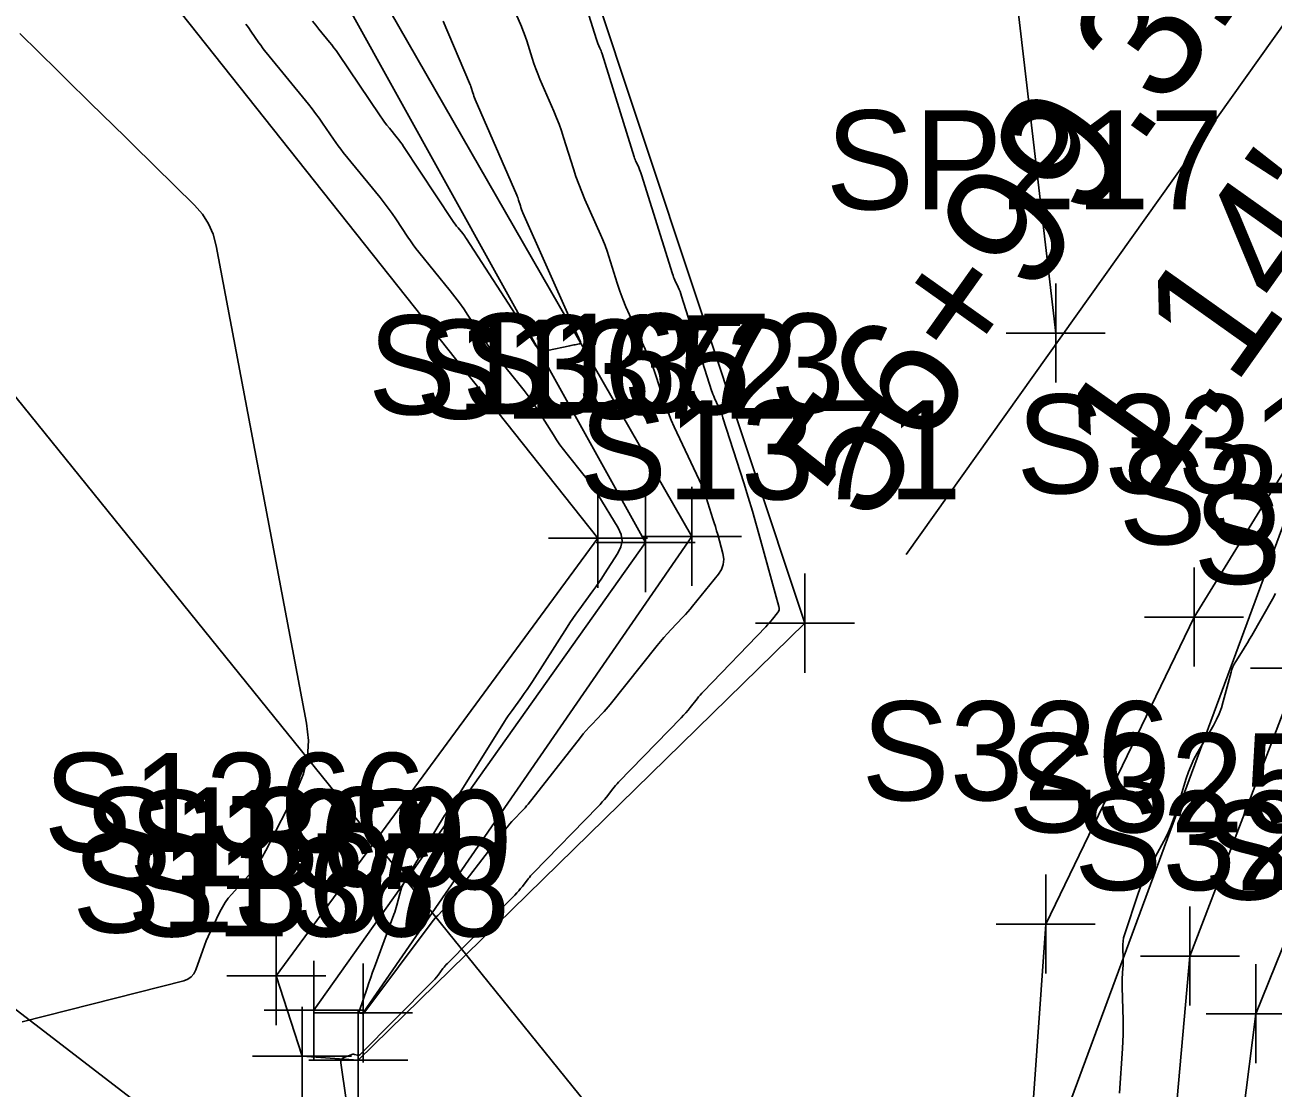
# Model space of a CAD drawing. Extents: x 816928 to 825690, y 436959 to 448212.
# Drawn here: x 818841.5 to 818891.9, y 445120.7 to 445163.6 of the extents above; entities that cross this region are included whole.
import ezdxf

# ---------------------------------------------------------------- set-up
doc = ezdxf.new("R2010")
doc.units = 0
for name, color, linetype in [('SURVEY - CENTERLINE - Preliminary', 7, 'Continuous'), ('SURVEY - CONTOURS - Intermediate with optional Text', 7, 'Continuous'), ('SURVEY - DRAINAGE - Area Shapes', 7, 'Continuous'), ('SURVEY - DRAINAGE - Bridge Hydraulic Data - Points - Locators', 7, 'Continuous'), ('SURVEY - DRAINAGE - Bridge Hydraulic Data - Points - Numbers', 7, 'Continuous'), ('SURVEY - DRAINAGE - Bridge Hydraulic Data with Text', 7, 'Continuous'), ('SURVEY - DRAINAGE - Bridges Text', 7, 'Continuous'), ('SURVEY - DTM - Breaklines', 7, 'Continuous'), ('SURVEY - DTM - Breaklines - Points - Locators', 7, 'Continuous'), ('SURVEY - DTM - Breaklines - Points - Numbers', 7, 'Continuous'), ('SURVEY - NON-TRANSPORTATION - Features', 7, 'Continuous'), ('SURVEY - PROPERTY - Parcels', 7, 'Continuous'), ('SURVEY - PROPERTY - ROW Lines', 7, 'Continuous'), ('SURVEY - VEGETATION - Features with Text', 7, 'Continuous')]:
    doc.layers.add(name, color=color, linetype=linetype)

msp = doc.modelspace()

# ---------------------------------------------------------------- linework, layer by layer
at = {"layer": 'SURVEY - CENTERLINE - Preliminary'}
msp.add_arc((819561.099, 444735.998), 738, 144.598464, 158.728454, dxfattribs=at)
msp.add_arc((819561.099, 444735.998), 738, 144.598464, 158.728454, dxfattribs=at)
at = {"layer": 'SURVEY - CONTOURS - Intermediate with optional Text'}
for points in [[(818855.834, 445110.685), (818854.239, 445121.709), (818854.239, 445121.783), (818854.26, 445121.845), (818854.303, 445121.895), (818854.368, 445121.931), (818854.654, 445122.043), (818854.689, 445122.054), (818854.725, 445122.059), (818854.76, 445122.058), (818854.797, 445122.051), (818854.916, 445122.019), (818854.94, 445122.016), (818854.963, 445122.018), (818854.984, 445122.027), (818855.004, 445122.043), (818857.908, 445124.953), (818857.978, 445125.026), (818858.045, 445125.1), (818858.109, 445125.177), (818858.171, 445125.257), (818858.367, 445125.52), (818858.411, 445125.575), (818858.455, 445125.629), (818858.502, 445125.682), (818858.551, 445125.733), (818861.269, 445128.491), (818861.349, 445128.575), (818861.427, 445128.662), (818861.502, 445128.75), (818861.574, 445128.841), (818861.806, 445129.143), (818861.856, 445129.207), (818861.908, 445129.269), (818861.963, 445129.33), (818862.019, 445129.389), (818864.628, 445132.062), (818864.717, 445132.155), (818864.803, 445132.251), (818864.886, 445132.348), (818864.966, 445132.448), (818865.225, 445132.779), (818865.281, 445132.849), (818865.339, 445132.917), (818865.399, 445132.984), (818865.461, 445133.05), (818867.987, 445135.656), (818868.081, 445135.756), (818868.174, 445135.859), (818868.263, 445135.963), (818868.351, 445136.07), (818868.631, 445136.423), (818868.692, 445136.498), (818868.755, 445136.572), (818868.82, 445136.644), (818868.886, 445136.714), (818871.405, 445139.329), (818871.475, 445139.403), (818871.543, 445139.479), (818871.609, 445139.556), (818871.674, 445139.634), (818871.883, 445139.894), (818871.92, 445139.951), (818871.941, 445140.011), (818871.946, 445140.075), (818871.935, 445140.142), (818871.196, 445142.842), (818871.034, 445143.42), (818870.867, 445143.996), (818870.693, 445144.57), (818870.514, 445145.143), (818869.674, 445147.772), (818869.636, 445147.885), (818869.594, 445147.997), (818869.549, 445148.107), (818869.499, 445148.216), (818869.333, 445148.569), (818869.299, 445148.645), (818869.267, 445148.722), (818869.238, 445148.801), (818869.211, 445148.88), (818868.006, 445152.685), (818867.975, 445152.777), (818867.942, 445152.868), (818867.906, 445152.957), (818867.867, 445153.046), (818867.735, 445153.334), (818867.708, 445153.397), (818867.683, 445153.459), (818867.659, 445153.523), (818867.638, 445153.587), (818866.381, 445157.587), (818866.357, 445157.661), (818866.33, 445157.734), (818866.302, 445157.806), (818866.271, 445157.877), (818866.168, 445158.109), (818866.147, 445158.159), (818866.127, 445158.21), (818866.108, 445158.261), (818866.091, 445158.313), (818864.79, 445162.48), (818864.771, 445162.538), (818864.75, 445162.596), (818864.728, 445162.653), (818864.705, 445162.709), (818864.625, 445162.892), (818864.609, 445162.932), (818864.593, 445162.972), (818864.579, 445163.012), (818864.566, 445163.053), (818863.872, 445165.287)], [(818850.409, 445163.677), (818850.512, 445163.536), (818850.613, 445163.393), (818850.936, 445162.922), (818851.007, 445162.822), (818851.079, 445162.723), (818851.153, 445162.626), (818851.23, 445162.53), (818852.933, 445160.445), (818853.082, 445160.258), (818853.227, 445160.067), (818853.368, 445159.873), (818853.504, 445159.676), (818853.943, 445159.028), (818854.038, 445158.89), (818854.137, 445158.754), (818854.238, 445158.621), (818854.342, 445158.49), (818855.826, 445156.668), (818855.993, 445156.458), (818856.155, 445156.243), (818856.312, 445156.025), (818856.463, 445155.803), (818856.948, 445155.071), (818857.054, 445154.915), (818857.163, 445154.762), (818857.277, 445154.612), (818857.394, 445154.465), (818858.663, 445152.902), (818858.851, 445152.664), (818859.032, 445152.422), (818859.207, 445152.175), (818859.375, 445151.923), (818859.913, 445151.092), (818860.031, 445150.915), (818860.153, 445150.742), (818860.279, 445150.572), (818860.411, 445150.406), (818861.427, 445149.15), (818861.64, 445148.88), (818861.843, 445148.604), (818862.039, 445148.322), (818862.226, 445148.034), (818862.825, 445147.084), (818862.956, 445146.882), (818863.093, 445146.684), (818863.235, 445146.491), (818863.383, 445146.302), (818864.074, 445145.445), (818864.219, 445145.259), (818864.357, 445145.069), (818864.49, 445144.875), (818864.616, 445144.676), (818865.445, 445143.32), (818865.562, 445143.063), (818865.599, 445142.808), (818865.556, 445142.553), (818865.432, 445142.299), (818864.895, 445141.473), (818864.779, 445141.297), (818864.661, 445141.122), (818864.54, 445140.949), (818864.417, 445140.778), (818863.849, 445140), (818863.729, 445139.833), (818863.611, 445139.664), (818863.496, 445139.492), (818863.384, 445139.319), (818861.979, 445137.117), (818861.872, 445136.953), (818861.763, 445136.79), (818861.651, 445136.629), (818861.537, 445136.469), (818861.159, 445135.952), (818861.079, 445135.84), (818861.001, 445135.727), (818860.926, 445135.613), (818860.852, 445135.497), (818858.997, 445132.524), (818858.944, 445132.44), (818858.889, 445132.357), (818858.833, 445132.276), (818858.775, 445132.195), (818858.584, 445131.933), (818858.544, 445131.876), (818858.505, 445131.819), (818858.467, 445131.761), (818858.431, 445131.702), (818856.841, 445129.075), (818856.771, 445128.949), (818856.711, 445128.819), (818856.661, 445128.685), (818856.62, 445128.547), (818856.505, 445128.088), (818856.479, 445127.99), (818856.451, 445127.892), (818856.419, 445127.796), (818856.386, 445127.701), (818855.603, 445125.583), (818855.525, 445125.372), (818855.449, 445125.16), (818855.375, 445124.947), (818855.302, 445124.734), (818854.981, 445123.79), (818854.977, 445123.767), (818854.981, 445123.749), (818854.994, 445123.735), (818855.016, 445123.726), (818855.108, 445123.701), (818855.121, 445123.699), (818855.133, 445123.7), (818855.145, 445123.705), (818855.155, 445123.713), (818855.187, 445123.746), (818855.194, 445123.753), (818855.201, 445123.76), (818855.207, 445123.767), (818855.213, 445123.775), (818857.937, 445127.415), (818857.988, 445127.481), (818858.042, 445127.545), (818858.098, 445127.608), (818858.155, 445127.669), (818858.348, 445127.864), (818858.388, 445127.906), (818858.428, 445127.95), (818858.466, 445127.995), (818858.502, 445128.041), (818860.884, 445131.144), (818860.969, 445131.251), (818861.057, 445131.356), (818861.148, 445131.458), (818861.243, 445131.557), (818861.555, 445131.878), (818861.621, 445131.947), (818861.685, 445132.018), (818861.747, 445132.091), (818861.807, 445132.166), (818863.919, 445134.863), (818864.031, 445135.002), (818864.146, 445135.138), (818864.265, 445135.271), (818864.388, 445135.401), (818864.794, 445135.82), (818864.88, 445135.911), (818864.964, 445136.004), (818865.045, 445136.099), (818865.124, 445136.196), (818867.015, 445138.574), (818867.149, 445138.739), (818867.287, 445138.9), (818867.429, 445139.058), (818867.574, 445139.212), (818868.055, 445139.712), (818868.157, 445139.82), (818868.257, 445139.93), (818868.353, 445140.043), (818868.448, 445140.157), (818869.494, 445141.456), (818869.618, 445141.648), (818869.688, 445141.852), (818869.705, 445142.067), (818869.668, 445142.293), (818869.461, 445143.051), (818869.416, 445143.212), (818869.369, 445143.374), (818869.32, 445143.535), (818869.27, 445143.695), (818868.996, 445144.554), (818868.934, 445144.737), (818868.866, 445144.917), (818868.793, 445145.095), (818868.714, 445145.271), (818867.705, 445147.41), (818867.583, 445147.681), (818867.47, 445147.955), (818867.367, 445148.233), (818867.272, 445148.514), (818866.979, 445149.44), (818866.914, 445149.637), (818866.842, 445149.832), (818866.764, 445150.024), (818866.681, 445150.215), (818865.895, 445151.935), (818865.758, 445152.249), (818865.63, 445152.566), (818865.512, 445152.888), (818865.404, 445153.213), (818865.068, 445154.282), (818864.993, 445154.509), (818864.912, 445154.735), (818864.824, 445154.958), (818864.73, 445155.178), (818864.101, 445156.594), (818863.97, 445156.899), (818863.849, 445157.207), (818863.736, 445157.519), (818863.633, 445157.834), (818863.239, 445159.094), (818863.152, 445159.363), (818863.057, 445159.629), (818862.955, 445159.892), (818862.846, 445160.153), (818862.281, 445161.455), (818862.195, 445161.662), (818862.114, 445161.871), (818862.039, 445162.082), (818861.97, 445162.295), (818861.752, 445162.994), (818861.704, 445163.143), (818861.652, 445163.291), (818861.596, 445163.437), (818861.536, 445163.582), (818861.029, 445164.764)], [(818853.105, 445163.798), (818853.231, 445163.634), (818853.36, 445163.473), (818853.787, 445162.95), (818853.877, 445162.836), (818853.965, 445162.721), (818854.05, 445162.605), (818854.132, 445162.486), (818855.835, 445159.967), (818855.922, 445159.84), (818856.013, 445159.716), (818856.106, 445159.593), (818856.202, 445159.473), (818856.519, 445159.083), (818856.586, 445158.999), (818856.651, 445158.913), (818856.714, 445158.826), (818856.774, 445158.737), (818858.759, 445155.743), (818858.811, 445155.667), (818858.864, 445155.592), (818858.92, 445155.518), (818858.977, 445155.446), (818859.167, 445155.212), (818859.207, 445155.162), (818859.246, 445155.11), (818859.283, 445155.057), (818859.319, 445155.004), (818861.623, 445151.446), (818861.634, 445151.43), (818861.645, 445151.414), (818861.656, 445151.399), (818861.668, 445151.384), (818861.708, 445151.335), (818861.716, 445151.324), (818861.724, 445151.314), (818861.732, 445151.302), (818861.739, 445151.291), (818862.124, 445150.68), (818862.216, 445150.569), (818862.324, 445150.5), (818862.449, 445150.471), (818862.592, 445150.484), (818863.49, 445150.682), (818863.542, 445150.693), (818863.595, 445150.704), (818863.648, 445150.714), (818863.701, 445150.724), (818863.874, 445150.756), (818863.904, 445150.766), (818863.922, 445150.783), (818863.926, 445150.807), (818863.917, 445150.838), (818863.552, 445151.635), (818863.547, 445151.647), (818863.542, 445151.66), (818863.538, 445151.672), (818863.533, 445151.685), (818863.52, 445151.726), (818863.517, 445151.735), (818863.514, 445151.744), (818863.511, 445151.753), (818863.507, 445151.761), (818861.599, 445156.054), (818861.57, 445156.123), (818861.542, 445156.193), (818861.517, 445156.264), (818861.493, 445156.335), (818861.42, 445156.57), (818861.403, 445156.62), (818861.386, 445156.67), (818861.367, 445156.719), (818861.346, 445156.768), (818859.669, 445160.634), (818859.643, 445160.699), (818859.617, 445160.763), (818859.594, 445160.829), (818859.573, 445160.895), (818859.505, 445161.112), (818859.49, 445161.159), (818859.474, 445161.204), (818859.457, 445161.25), (818859.438, 445161.295), (818858.37, 445163.788)], [(818841.277, 445163.296), (818842.818, 445161.782), (818843.148, 445161.457), (818843.478, 445161.133), (818843.808, 445160.808), (818844.139, 445160.484), (818845.528, 445159.119), (818845.826, 445158.826), (818846.124, 445158.533), (818846.421, 445158.241), (818846.719, 445157.948), (818848.336, 445156.359), (818848.651, 445156.001), (818848.901, 445155.61), (818849.088, 445155.184), (818849.21, 445154.723), (818852.86, 445135.438), (818852.937, 445134.738), (818852.897, 445134.054), (818852.742, 445133.387), (818852.47, 445132.736), (818851.216, 445130.292), (818851.067, 445130.022), (818850.9, 445129.764), (818850.717, 445129.516), (818850.518, 445129.281), (818849.839, 445128.529), (818849.7, 445128.364), (818849.574, 445128.19), (818849.461, 445128.007), (818849.361, 445127.816), (818848.969, 445126.992), (818848.887, 445126.815), (818848.81, 445126.636), (818848.737, 445126.455), (818848.669, 445126.271), (818848.382, 445125.467), (818848.306, 445125.311), (818848.201, 445125.186), (818848.067, 445125.093), (818847.904, 445125.032), (818841.375, 445123.369)], [(818891.99, 445140.675), (818891.87, 445140.446), (818891.025, 445138.974), (818890.94, 445138.828), (818890.853, 445138.682), (818890.765, 445138.538), (818890.675, 445138.394), (818890.379, 445137.926), (818890.319, 445137.824), (818890.268, 445137.718), (818890.226, 445137.609), (818890.191, 445137.496), (818889.876, 445136.31), (818889.801, 445136.059), (818889.709, 445135.815), (818889.602, 445135.577), (818889.478, 445135.346), (818888.826, 445134.219), (818888.694, 445133.975), (818888.576, 445133.724), (818888.472, 445133.466), (818888.383, 445133.203), (818887.957, 445131.813), (818887.858, 445131.518), (818887.745, 445131.229), (818887.619, 445130.946), (818887.478, 445130.668), (818886.873, 445129.547), (818886.749, 445129.305), (818886.636, 445129.057), (818886.534, 445128.805), (818886.442, 445128.549), (818885.892, 445126.888), (818885.855, 445126.759), (818885.83, 445126.629), (818885.817, 445126.496), (818885.816, 445126.362), (818885.831, 445125.921), (818885.833, 445125.826), (818885.833, 445125.732), (818885.83, 445125.638), (818885.825, 445125.543), (818885.797, 445125.127), (818885.792, 445125.038), (818885.789, 445124.949), (818885.789, 445124.86), (818885.791, 445124.771), (818885.833, 445123.435), (818885.838, 445123.149), (818885.837, 445122.863), (818885.828, 445122.577), (818885.812, 445122.291), (818885.688, 445120.495)]]:
    msp.add_lwpolyline(points, dxfattribs=at)
at = {"layer": 'SURVEY - DRAINAGE - Area Shapes'}
msp.add_arc((819561.099, 444735.998), 738, 144.598464, 158.728454, dxfattribs=at)
at = {"layer": 'SURVEY - DRAINAGE - Bridge Hydraulic Data - Points - Locators'}
for p, q in [((818883.11, 445153.193), (818883.11, 445149.193)), ((818885.11, 445151.193), (818881.11, 445151.193)), ((818864.623, 445144.909), (818864.623, 445140.909)), ((818866.623, 445142.909), (818862.623, 445142.909)), ((818872.985, 445141.475), (818872.985, 445137.475)), ((818874.985, 445139.475), (818870.985, 445139.475)), ((818851.635, 445127.23), (818851.635, 445123.23)), ((818853.635, 445125.23), (818849.635, 445125.23)), ((818852.677, 445123.979), (818852.677, 445119.979)), ((818854.948, 445123.819), (818854.948, 445119.819)), ((818854.677, 445121.979), (818850.677, 445121.979)), ((818856.948, 445121.819), (818852.948, 445121.819))]:
    msp.add_line(p, q, dxfattribs=at)
at = {"layer": 'SURVEY - DRAINAGE - Bridge Hydraulic Data with Text'}
msp.add_line((818883.11, 445151.193), (818874.403, 445225.686), dxfattribs=at)
for points in [[(818784.519, 445183.127), (818807.177, 445189.01), (818822.594, 445179.409), (818846.448, 445165.831), (818864.623, 445142.909), (818851.635, 445125.23), (818852.677, 445121.979), (818854.948, 445121.819)], [(818854.948, 445121.819), (818872.985, 445139.475), (818864.238, 445165.76), (818877.5, 445170.98), (818901.426, 445180.025), (818910.363, 445177.537), (818911.769, 445177.181)]]:
    msp.add_lwpolyline(points, dxfattribs=at)
at = {"layer": 'SURVEY - DRAINAGE - Bridges Text'}
msp.add_line((818898.784, 445172.789), (818877.079, 445142.249), dxfattribs=at)
at = {"layer": 'SURVEY - DTM - Breaklines'}
for points in [[(818855.139, 445123.73), (818868.422, 445142.981), (818854.455, 445167.294), (818858.57, 445175.647), (818857.013, 445179.498)], [(818853.152, 445123.838), (818866.552, 445142.733), (818852.525, 445168.017), (818857.339, 445175.88), (818856.138, 445179.015)], [(818668.595, 444528.248), (818685.72, 444574.968), (818701.794, 444621.45), (818719.062, 444668.194), (818736.238, 444715.249), (818753.948, 444762.85), (818774.464, 444810.969), (818792.449, 444864.448), (818805.628, 444902.916), (818824.667, 444952.978), (818842.703, 444999.992), (818860.037, 445043.657), (818874.783, 445092.697), (818880.828, 445100.462), (818882.708, 445127.319), (818888.697, 445139.719), (818911.769, 445177.181)], [(818808.76, 444902.23), (818827.799, 444952.151), (818848.589, 444997.649), (818865.395, 445041.972), (818883.078, 445086.424), (818886.189, 445099.702), (818888.533, 445126.027), (818892.982, 445137.658), (818915.716, 445177.345)], [(818674.595, 444526.594), (818691.482, 444572.447), (818707.878, 444620.16), (818723.912, 444667.229), (818740.639, 444713.784), (818759.184, 444760.748), (818780.007, 444808.946), (818796, 444863.508), (818810.795, 444901.838), (818829.914, 444950.597), (818849.199, 444995.994), (818867.147, 445042.084), (818885.66, 445087.698), (818887.911, 445097.82), (818891.186, 445123.694), (818896.177, 445136.062), (818917.377, 445175.791)]]:
    msp.add_lwpolyline(points, dxfattribs=at)
at = {"layer": 'SURVEY - DTM - Breaklines - Points - Locators'}
for p, q in [((818866.552, 445144.733), (818866.552, 445140.733)), ((818868.422, 445144.981), (818868.422, 445140.981)), ((818868.552, 445142.733), (818864.552, 445142.733)), ((818870.422, 445142.981), (818866.422, 445142.981)), ((818888.697, 445141.719), (818888.697, 445137.719)), ((818890.697, 445139.719), (818886.697, 445139.719)), ((818894.982, 445137.658), (818890.982, 445137.658)), ((818882.708, 445129.319), (818882.708, 445125.319)), ((818888.533, 445128.027), (818888.533, 445124.027)), ((818884.708, 445127.319), (818880.708, 445127.319)), ((818890.533, 445126.027), (818886.533, 445126.027)), ((818853.152, 445125.838), (818853.152, 445121.838)), ((818855.139, 445125.73), (818855.139, 445121.73)), ((818891.186, 445125.694), (818891.186, 445121.694)), ((818855.152, 445123.838), (818851.152, 445123.838)), ((818857.139, 445123.73), (818853.139, 445123.73)), ((818893.186, 445123.694), (818889.186, 445123.694))]:
    msp.add_line(p, q, dxfattribs=at)
at = {"layer": 'SURVEY - NON-TRANSPORTATION - Features'}
msp.add_lwpolyline([(818878.723, 445102.028), (818832.174, 445159.68), (818783.535, 445180.107), (818767.737, 445165.919), (818720.129, 445113.759)], dxfattribs=at)
at = {"layer": 'SURVEY - PROPERTY - Parcels'}
msp.add_arc((819561.099, 444735.998), 763, 144.598464, 158.728454, dxfattribs=at)
at = {"layer": 'SURVEY - PROPERTY - ROW Lines'}
msp.add_arc((819561.099, 444735.998), 763, 144.598464, 158.728454, dxfattribs=at)
msp.add_arc((819561.099, 444735.998), 763, 144.598464, 158.728454, dxfattribs=at)
at = {"layer": 'SURVEY - VEGETATION - Features with Text'}
for points in [[(818921.649, 445531.075), (818911.357, 445419.447), (818895.02, 445347.602), (818900.539, 445320.739), (818919.801, 445285.725), (818871.556, 445256.506), (818910.143, 445268.505), (818928.958, 445242.751), (818875.35, 445097.529)], [(818875.35, 445097.529), (818816.87, 445142.523), (818782.15, 445116.559), (818758.749, 445085.99), (818745.74, 445051.115), (818754.139, 445016.546)]]:
    msp.add_lwpolyline(points, dxfattribs=at)

# ---------------------------------------------------------------- texts
at = {"layer": 'SURVEY - DRAINAGE - Bridge Hydraulic Data - Points - Numbers'}
for s, p in [('SP217', (818873.823, 445156.193)), ('S1365', (818855.335, 445147.909)), ('S1371', (818863.854, 445144.475)), ('S1366', (818842.237, 445130.23)), ('S1367', (818843.389, 445126.979)), ('S1368', (818845.613, 445126.819))]:
    msp.add_text(s, height=4, dxfattribs=at).set_placement(p)
at = {"layer": 'SURVEY - DRAINAGE - Bridges Text'}
for s, p in [('56+99.31', (818875.551, 445143.336)), ("1.14'", (818887.084, 445144.458))]:
    msp.add_text(s, height=5, rotation=54.5985, dxfattribs=at).set_placement(p)
at = {"layer": 'SURVEY - DTM - Breaklines - Points - Numbers'}
for s, p in [('S1372', (818857.265, 445147.733)), ('S1373', (818859.134, 445147.981)), ('S331', (818881.518, 445144.719)), ('S332', (818885.646, 445142.658)), ('S330', (818888.668, 445141.062)), ('S326', (818875.262, 445132.319)), ('S325', (818881.197, 445131.027)), ('S1369', (818843.849, 445128.838)), ('S1370', (818845.678, 445128.73)), ('S327', (818883.85, 445128.694)), ('S328', (818889.099, 445128.312))]:
    msp.add_text(s, height=4, dxfattribs=at).set_placement(p)

doc.saveas('drawing.dxf')
